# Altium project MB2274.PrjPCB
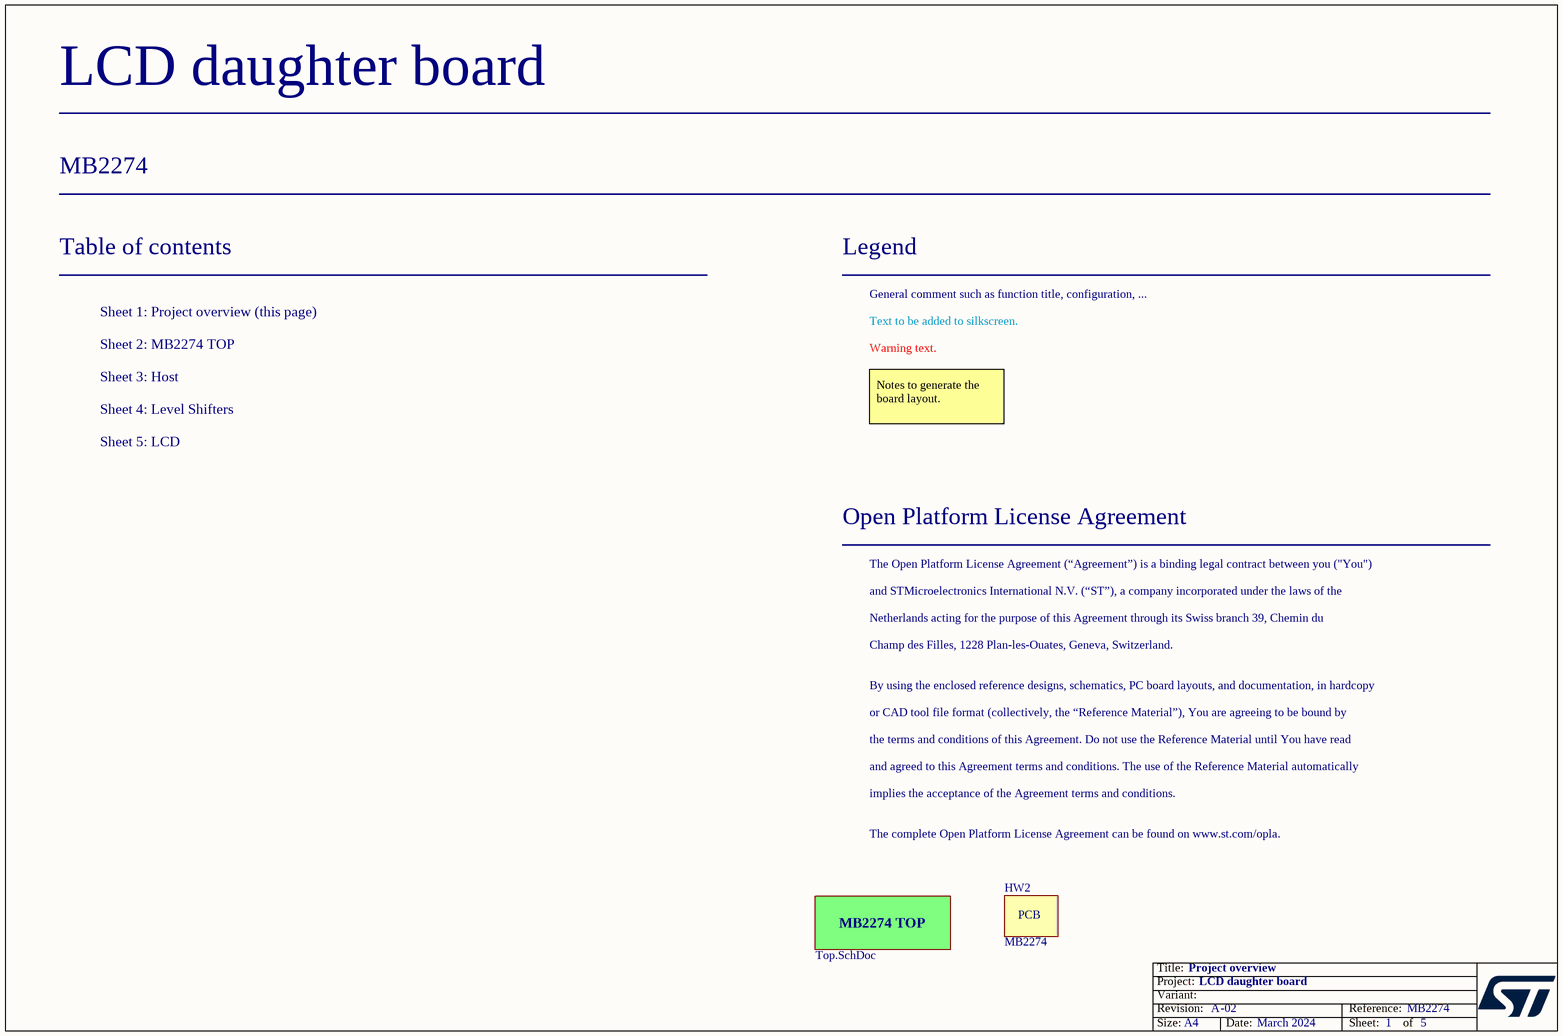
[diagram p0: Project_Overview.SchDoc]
Board_Reference: MB2274; Board_PCB_Revision: A; Board_Name: LCD daughter board; Board_Document_Date: March 2024; Board_Assembly_Revision: 02
5 sheets, 38 parts. Net scope: flat (ports and power ports of the same name join across sheets).
Board file: MB2274.PcbDoc
Sheets:
  Project_Overview.SchDoc
    MB2274 TOP = Top.SchDoc
      Host = Host.SchDoc
      Level Shifter = Level_Shifter.SchDoc
      LCD = LCD.SchDoc

## Sheet Project_Overview.SchDoc: Project overview
size A4; Date: Not used; ApprovedBy: Not used; CheckedBy: Not used; Author: Not used; CompanyName: STMicroelectronics; DrawnBy: Not used; Engineer: Not used; Organization: Not used; Address1: Not used; Address2: Not used; Address3: Not used; Address4: Not used; DocumentNumber: 1; Revision: Not used; SheetNumber: 1; SheetTotal: 5

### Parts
HW2  value MB2274  (hidden comment: PCB)

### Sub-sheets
MB2274 TOP = Top.SchDoc: no entries

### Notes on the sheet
- Table of contents
- Legend
- General comment such as function title, configuration, ...
- Text to be added to silkscreen.
- Warning text.
- Notes to generate the board layout.
- Sheet 1: Project overview (this page)
  Sheet 2: MB2274 TOP
  Sheet 3: Host
  Sheet 4: Level Shifters
  Sheet 5: LCD
- Open Platform License Agreement
- The Open Platform License Agreement (“Agreement”) is a binding legal contract between you ("You")
- and STMicroelectronics International N.V. (“ST”), a company incorporated under the laws of the
- Netherlands acting for the purpose of this Agreement through its Swiss branch 39, Chemin du
- Champ des Filles, 1228 Plan-les-Ouates, Geneva, Switzerland.
- By using the enclosed reference designs, schematics, PC board layouts, and documentation, in hardcopy
- or CAD tool file format (collectively, the “Reference Material”), You are agreeing to be bound by
- the terms and conditions of this Agreement. Do not use the Reference Material until You have read
- and agreed to this Agreement terms and conditions. The use of the Reference Material automatically
- implies the acceptance of the Agreement terms and conditions.
- The complete Open Platform License Agreement can be found on www.st.com/opla.

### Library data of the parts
HW2 = MCD-04586: PCB, MB2274, 4.3inches_TFT_LCD; Part_Preference: Recommended; Manufacturer: H-FAST; ShowFields: YES; ID: 6702

## Sheet Top.SchDoc: Schematic sheet title to update
size A4; Date: Not used; ApprovedBy: Not used; CheckedBy: Not used; Author: Not used; CompanyName: STMicroelectronics; DrawnBy: Not used; Engineer: Not used; Organization: Not used; Address1: Not used; Address2: Not used; Address3: Not used; Address4: Not used; DocumentNumber: 2; Revision: Not used; SheetNumber: 2; SheetTotal: 5
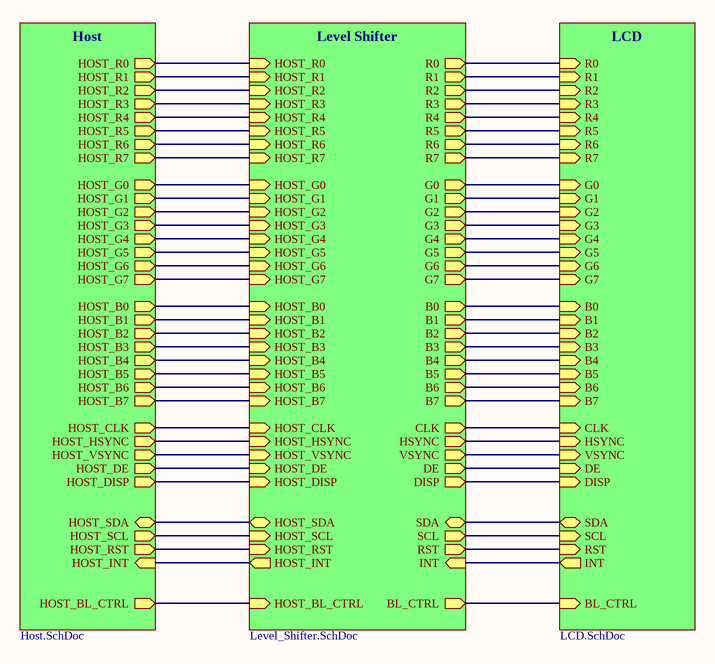
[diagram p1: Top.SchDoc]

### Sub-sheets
Host = Host.SchDoc: HOST_R0 (out), HOST_R1 (out), HOST_R2 (out), HOST_R3 (out), HOST_R4 (out), HOST_R5 (out), HOST_R6 (out), HOST_R7 (out), HOST_G0 (out), HOST_G1 (out), HOST_G2 (out), HOST_G3 (out), HOST_G4 (out), HOST_G5 (out), HOST_G6 (out), HOST_G7 (out), HOST_B0 (out), HOST_B1 (out), HOST_B2 (out), HOST_B3 (out), HOST_B4 (out), HOST_B5 (out), HOST_B6 (out), HOST_B7 (out), HOST_CLK (out), HOST_HSYNC (out), HOST_VSYNC (out), HOST_DE (out), HOST_DISP (out), HOST_SDA (bidir), HOST_SCL (out), HOST_RST (out), HOST_INT (in), HOST_BL_CTRL (out)
LCD = LCD.SchDoc: BL_CTRL (in), R0 (in), R1 (in), R2 (in), R3 (in), R4 (in), R5 (in), R6 (in), R7 (in), G0 (in), G1 (in), G2 (in), G3 (in), G4 (in), G5 (in), G6 (in), G7 (in), B0 (in), B1 (in), B2 (in), B3 (in), B4 (in), B5 (in), B6 (in), B7 (in), CLK (in), HSYNC (in), VSYNC (in), DE (in), DISP (in), SCL (in), SDA (bidir), RST (in), INT (out)
Level Shifter = Level_Shifter.SchDoc: HOST_R0 (in), HOST_R1 (in), HOST_R2 (in), HOST_R3 (in), HOST_R4 (in), HOST_R5 (in), HOST_R6 (in), HOST_R7 (in), HOST_G0 (in), HOST_G1 (in), HOST_G2 (in), HOST_G3 (in), HOST_G4 (in), HOST_G5 (in), HOST_G6 (in), HOST_G7 (in), HOST_B0 (in), HOST_B1 (in), HOST_B2 (in), HOST_B3 (in), HOST_B4 (in), HOST_B5 (in), HOST_B6 (in), HOST_B7 (in), HOST_CLK (in), HOST_HSYNC (in), HOST_VSYNC (in), HOST_DE (in), HOST_DISP (in), HOST_SDA (bidir), HOST_SCL (in), HOST_RST (in), HOST_INT (out), HOST_BL_CTRL (in), R0 (out), R1 (out), R2 (out), R3 (out), R4 (out), R5 (out), R6 (out), R7 (out), G0 (out), G1 (out), G2 (out), G3 (out), G4 (out), G5 (out), G6 (out), G7 (out), B0 (out), B1 (out), B2 (out), B3 (out), B4 (out), B5 (out), B6 (out), B7 (out), CLK (out), HSYNC (out), VSYNC (out), DE (out), DISP (out), SDA (bidir), SCL (out), RST (out), INT (in), BL_CTRL (out)

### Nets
(unnamed): sheet Host/HOST_R0, sheet Level Shifter/HOST_R0
(unnamed): sheet Host/HOST_R1, sheet Level Shifter/HOST_R1  [a separate net that carries the same name]
(unnamed): sheet Host/HOST_R2, sheet Level Shifter/HOST_R2  [a separate net that carries the same name]
(unnamed): sheet Host/HOST_R3, sheet Level Shifter/HOST_R3  [a separate net that carries the same name]
(unnamed): sheet Host/HOST_R4, sheet Level Shifter/HOST_R4  [a separate net that carries the same name]
(unnamed): sheet Host/HOST_R5, sheet Level Shifter/HOST_R5  [a separate net that carries the same name]
(unnamed): sheet Host/HOST_R6, sheet Level Shifter/HOST_R6  [a separate net that carries the same name]
(unnamed): sheet Host/HOST_R7, sheet Level Shifter/HOST_R7  [a separate net that carries the same name]
(unnamed): sheet Host/HOST_G0, sheet Level Shifter/HOST_G0  [a separate net that carries the same name]
(unnamed): sheet Host/HOST_G1, sheet Level Shifter/HOST_G1  [a separate net that carries the same name]
(unnamed): sheet Host/HOST_G2, sheet Level Shifter/HOST_G2  [a separate net that carries the same name]
(unnamed): sheet Host/HOST_G3, sheet Level Shifter/HOST_G3  [a separate net that carries the same name]
(unnamed): sheet Host/HOST_G4, sheet Level Shifter/HOST_G4  [a separate net that carries the same name]
(unnamed): sheet Host/HOST_G5, sheet Level Shifter/HOST_G5  [a separate net that carries the same name]
(unnamed): sheet Host/HOST_G6, sheet Level Shifter/HOST_G6  [a separate net that carries the same name]
(unnamed): sheet Host/HOST_G7, sheet Level Shifter/HOST_G7  [a separate net that carries the same name]
(unnamed): sheet Host/HOST_B0, sheet Level Shifter/HOST_B0  [a separate net that carries the same name]
(unnamed): sheet Host/HOST_B1, sheet Level Shifter/HOST_B1  [a separate net that carries the same name]
(unnamed): sheet Host/HOST_B2, sheet Level Shifter/HOST_B2  [a separate net that carries the same name]
(unnamed): sheet Host/HOST_B3, sheet Level Shifter/HOST_B3  [a separate net that carries the same name]
(unnamed): sheet Host/HOST_B4, sheet Level Shifter/HOST_B4  [a separate net that carries the same name]
(unnamed): sheet Host/HOST_B5, sheet Level Shifter/HOST_B5  [a separate net that carries the same name]
(unnamed): sheet Host/HOST_B6, sheet Level Shifter/HOST_B6  [a separate net that carries the same name]
(unnamed): sheet Host/HOST_B7, sheet Level Shifter/HOST_B7  [a separate net that carries the same name]
(unnamed): sheet Host/HOST_CLK, sheet Level Shifter/HOST_CLK  [a separate net that carries the same name]
(unnamed): sheet Host/HOST_HSYNC, sheet Level Shifter/HOST_HSYNC  [a separate net that carries the same name]
(unnamed): sheet Host/HOST_VSYNC, sheet Level Shifter/HOST_VSYNC  [a separate net that carries the same name]
(unnamed): sheet Host/HOST_DE, sheet Level Shifter/HOST_DE  [a separate net that carries the same name]
(unnamed): sheet Host/HOST_DISP, sheet Level Shifter/HOST_DISP  [a separate net that carries the same name]
(unnamed): sheet Host/HOST_SDA, sheet Level Shifter/HOST_SDA  [a separate net that carries the same name]
(unnamed): sheet Host/HOST_SCL, sheet Level Shifter/HOST_SCL  [a separate net that carries the same name]
(unnamed): sheet Host/HOST_RST, sheet Level Shifter/HOST_RST  [a separate net that carries the same name]
(unnamed): sheet Host/HOST_INT, sheet Level Shifter/HOST_INT  [a separate net that carries the same name]
(unnamed): sheet Host/HOST_BL_CTRL, sheet Level Shifter/HOST_BL_CTRL  [a separate net that carries the same name]
(unnamed): sheet Level Shifter/R0, sheet LCD/R0  [a separate net that carries the same name]
(unnamed): sheet Level Shifter/R1, sheet LCD/R1  [a separate net that carries the same name]
(unnamed): sheet Level Shifter/R2, sheet LCD/R2  [a separate net that carries the same name]
(unnamed): sheet Level Shifter/R3, sheet LCD/R3  [a separate net that carries the same name]
(unnamed): sheet Level Shifter/R4, sheet LCD/R4  [a separate net that carries the same name]
(unnamed): sheet Level Shifter/R5, sheet LCD/R5  [a separate net that carries the same name]
(unnamed): sheet Level Shifter/R6, sheet LCD/R6  [a separate net that carries the same name]
(unnamed): sheet Level Shifter/R7, sheet LCD/R7  [a separate net that carries the same name]
(unnamed): sheet Level Shifter/G0, sheet LCD/G0  [a separate net that carries the same name]
(unnamed): sheet Level Shifter/G1, sheet LCD/G1  [a separate net that carries the same name]
(unnamed): sheet Level Shifter/G2, sheet LCD/G2  [a separate net that carries the same name]
(unnamed): sheet Level Shifter/G3, sheet LCD/G3  [a separate net that carries the same name]
(unnamed): sheet Level Shifter/G4, sheet LCD/G4  [a separate net that carries the same name]
(unnamed): sheet Level Shifter/G5, sheet LCD/G5  [a separate net that carries the same name]
(unnamed): sheet Level Shifter/G6, sheet LCD/G6  [a separate net that carries the same name]
(unnamed): sheet Level Shifter/G7, sheet LCD/G7  [a separate net that carries the same name]
(unnamed): sheet Level Shifter/B0, sheet LCD/B0  [a separate net that carries the same name]
(unnamed): sheet Level Shifter/B1, sheet LCD/B1  [a separate net that carries the same name]
(unnamed): sheet Level Shifter/B2, sheet LCD/B2  [a separate net that carries the same name]
(unnamed): sheet Level Shifter/B3, sheet LCD/B3  [a separate net that carries the same name]
(unnamed): sheet Level Shifter/B4, sheet LCD/B4  [a separate net that carries the same name]
(unnamed): sheet Level Shifter/B5, sheet LCD/B5  [a separate net that carries the same name]
(unnamed): sheet Level Shifter/B6, sheet LCD/B6  [a separate net that carries the same name]
(unnamed): sheet Level Shifter/B7, sheet LCD/B7  [a separate net that carries the same name]
(unnamed): sheet Level Shifter/CLK, sheet LCD/CLK  [a separate net that carries the same name]
(unnamed): sheet Level Shifter/HSYNC, sheet LCD/HSYNC  [a separate net that carries the same name]
(unnamed): sheet Level Shifter/VSYNC, sheet LCD/VSYNC  [a separate net that carries the same name]
(unnamed): sheet Level Shifter/DE, sheet LCD/DE  [a separate net that carries the same name]
(unnamed): sheet Level Shifter/DISP, sheet LCD/DISP  [a separate net that carries the same name]
(unnamed): sheet Level Shifter/SDA, sheet LCD/SDA  [a separate net that carries the same name]
(unnamed): sheet Level Shifter/SCL, sheet LCD/SCL  [a separate net that carries the same name]
(unnamed): sheet Level Shifter/RST, sheet LCD/RST  [a separate net that carries the same name]
(unnamed): sheet Level Shifter/INT, sheet LCD/INT  [a separate net that carries the same name]
(unnamed): sheet Level Shifter/BL_CTRL, sheet LCD/BL_CTRL  [a separate net that carries the same name]

## Sheet Host.SchDoc: Host Connection
size A4; Date: Not used; ApprovedBy: Not used; CheckedBy: Not used; Author: Not used; CompanyName: STMicroelectronics; DrawnBy: Not used; Engineer: Not used; Organization: Not used; Address1: Not used; Address2: Not used; Address3: Not used; Address4: Not used; DocumentNumber: 3; Revision: Not used; SheetNumber: 3; SheetTotal: 5
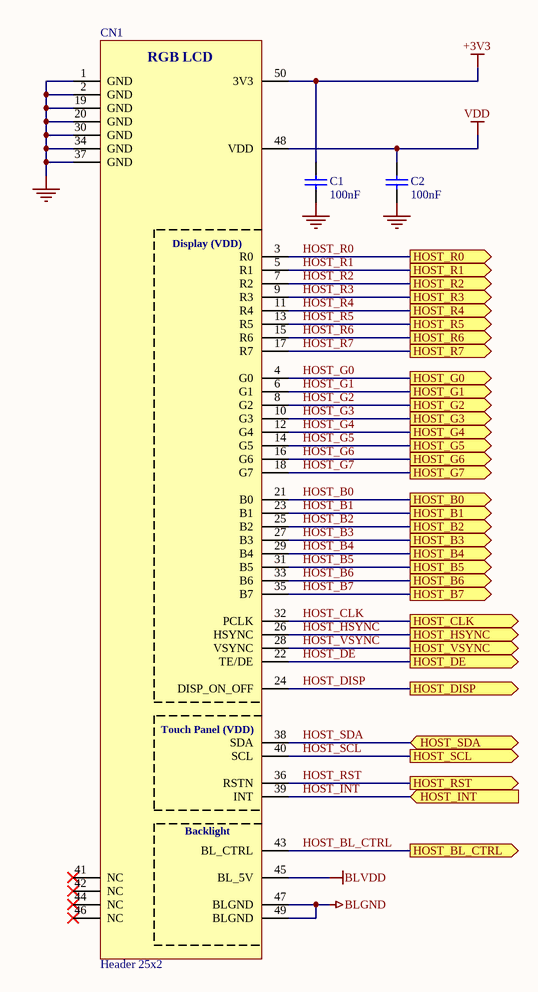
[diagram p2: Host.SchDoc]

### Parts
C1  100nF  [C0603]
C2  100nF  [C0603]
CN1  value Header 25x2  [CON_SAMTEC_FTSH-125-01-F-DV-K]  (hidden comment: Header 25x2 LCD MODULE)

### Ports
HOST_B0 (out), HOST_B1 (out), HOST_B2 (out), HOST_B3 (out), HOST_B4 (out), HOST_B5 (out), HOST_B6 (out), HOST_B7 (out), HOST_BL_CTRL (out), HOST_CLK (out), HOST_DE (out), HOST_DISP (out), HOST_G0 (out), HOST_G1 (out), HOST_G2 (out), HOST_G3 (out), HOST_G4 (out), HOST_G5 (out), HOST_G6 (out), HOST_G7 (out), HOST_HSYNC (out), HOST_INT (in), HOST_R0 (out), HOST_R1 (out), HOST_R2 (out), HOST_R3 (out), HOST_R4 (out), HOST_R5 (out), HOST_R6 (out), HOST_R7 (out), HOST_RST (out), HOST_SCL (out), HOST_SDA (bidir), HOST_VSYNC (out)

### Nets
+3V3: C1.2 CN1.50(3V3)
BLGND: CN1.47(BLGND) CN1.49(BLGND)
BLVDD: CN1.45(BL_5V)
GND: C1.1 C2.1 CN1.1(GND) CN1.2(GND) CN1.19(GND) CN1.20(GND) CN1.30(GND) CN1.34(GND) CN1.37(GND)
VDD: C2.2 CN1.48(VDD)
HOST_B0: CN1.21(B0) ; port HOST_B0
HOST_B1: CN1.23(B1) ; port HOST_B1
HOST_B2: CN1.25(B2) ; port HOST_B2
HOST_B3: CN1.27(B3) ; port HOST_B3
HOST_B4: CN1.29(B4) ; port HOST_B4
HOST_B5: CN1.31(B5) ; port HOST_B5
HOST_B6: CN1.33(B6) ; port HOST_B6
HOST_B7: CN1.35(B7) ; port HOST_B7
HOST_BL_CTRL: CN1.43(BL_CTRL) ; port HOST_BL_CTRL
HOST_CLK: CN1.32(PCLK) ; port HOST_CLK
HOST_DE: CN1.22(TE/DE) ; port HOST_DE
HOST_DISP: CN1.24(DISP_ON_OFF) ; port HOST_DISP
HOST_G0: CN1.4(G0) ; port HOST_G0
HOST_G1: CN1.6(G1) ; port HOST_G1
HOST_G2: CN1.8(G2) ; port HOST_G2
HOST_G3: CN1.10(G3) ; port HOST_G3
HOST_G4: CN1.12(G4) ; port HOST_G4
HOST_G5: CN1.14(G5) ; port HOST_G5
HOST_G6: CN1.16(G6) ; port HOST_G6
HOST_G7: CN1.18(G7) ; port HOST_G7
HOST_HSYNC: CN1.26(HSYNC) ; port HOST_HSYNC
HOST_INT: CN1.39(INT) ; port HOST_INT
HOST_R0: CN1.3(R0) ; port HOST_R0
HOST_R1: CN1.5(R1) ; port HOST_R1
HOST_R2: CN1.7(R2) ; port HOST_R2
HOST_R3: CN1.9(R3) ; port HOST_R3
HOST_R4: CN1.11(R4) ; port HOST_R4
HOST_R5: CN1.13(R5) ; port HOST_R5
HOST_R6: CN1.15(R6) ; port HOST_R6
HOST_R7: CN1.17(R7) ; port HOST_R7
HOST_RST: CN1.36(RSTN) ; port HOST_RST
HOST_SCL: CN1.40(SCL) ; port HOST_SCL
HOST_SDA: CN1.38(SDA) ; port HOST_SDA
HOST_VSYNC: CN1.28(VSYNC) ; port HOST_VSYNC

Not connected (* = marked no-connect by the designer): CN1 41(NC)* 42(NC)* 44(NC)* 46(NC)*

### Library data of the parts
C1 C2 = MCD-00211: Capacitor, MLCC, 100nF, 16V, X7R, +/-10%, 0603, T=0.8mm; Part_Preference: Recommended; Manufacturer: YAGEO; Manufacturer_Part_Number: CC0603KRX7R7BB104; Partial_Alternate_Internal_Part_Number: MCD-01099; Order_Code_RS: 669-8763; Component_Country_Of_Origin: China; ShowFields: YES; ID: 2659
CN1 = MCD-01187: Header, 25x2, 1.27mm, VR, SMD, T=5.97mm; Part_Type: Connector; Part_Preference: Recommended; Manufacturer: SAMTEC; Manufacturer_Part_Number: FTSH-125-01-F-DV-K; Partial_Alternate_Internal_Part_Number: MCD-03150; Order_Code_RS: 208-1518; Component_Country_Of_Origin: China, Costa Rica, Malaysia, USA, Vietnam; ShowFields: YES; ID: 3304

## Sheet Level_Shifter.SchDoc: Level Shifters
size A3; Date: Not used; ApprovedBy: Not used; CheckedBy: Not used; Author: Not used; CompanyName: STMicroelectronics; DrawnBy: Not used; Engineer: Not used; Organization: Not used; Address1: Not used; Address2: Not used; Address3: Not used; Address4: Not used; DocumentNumber: 4; Revision: Not used; SheetNumber: 4; SheetTotal: 5
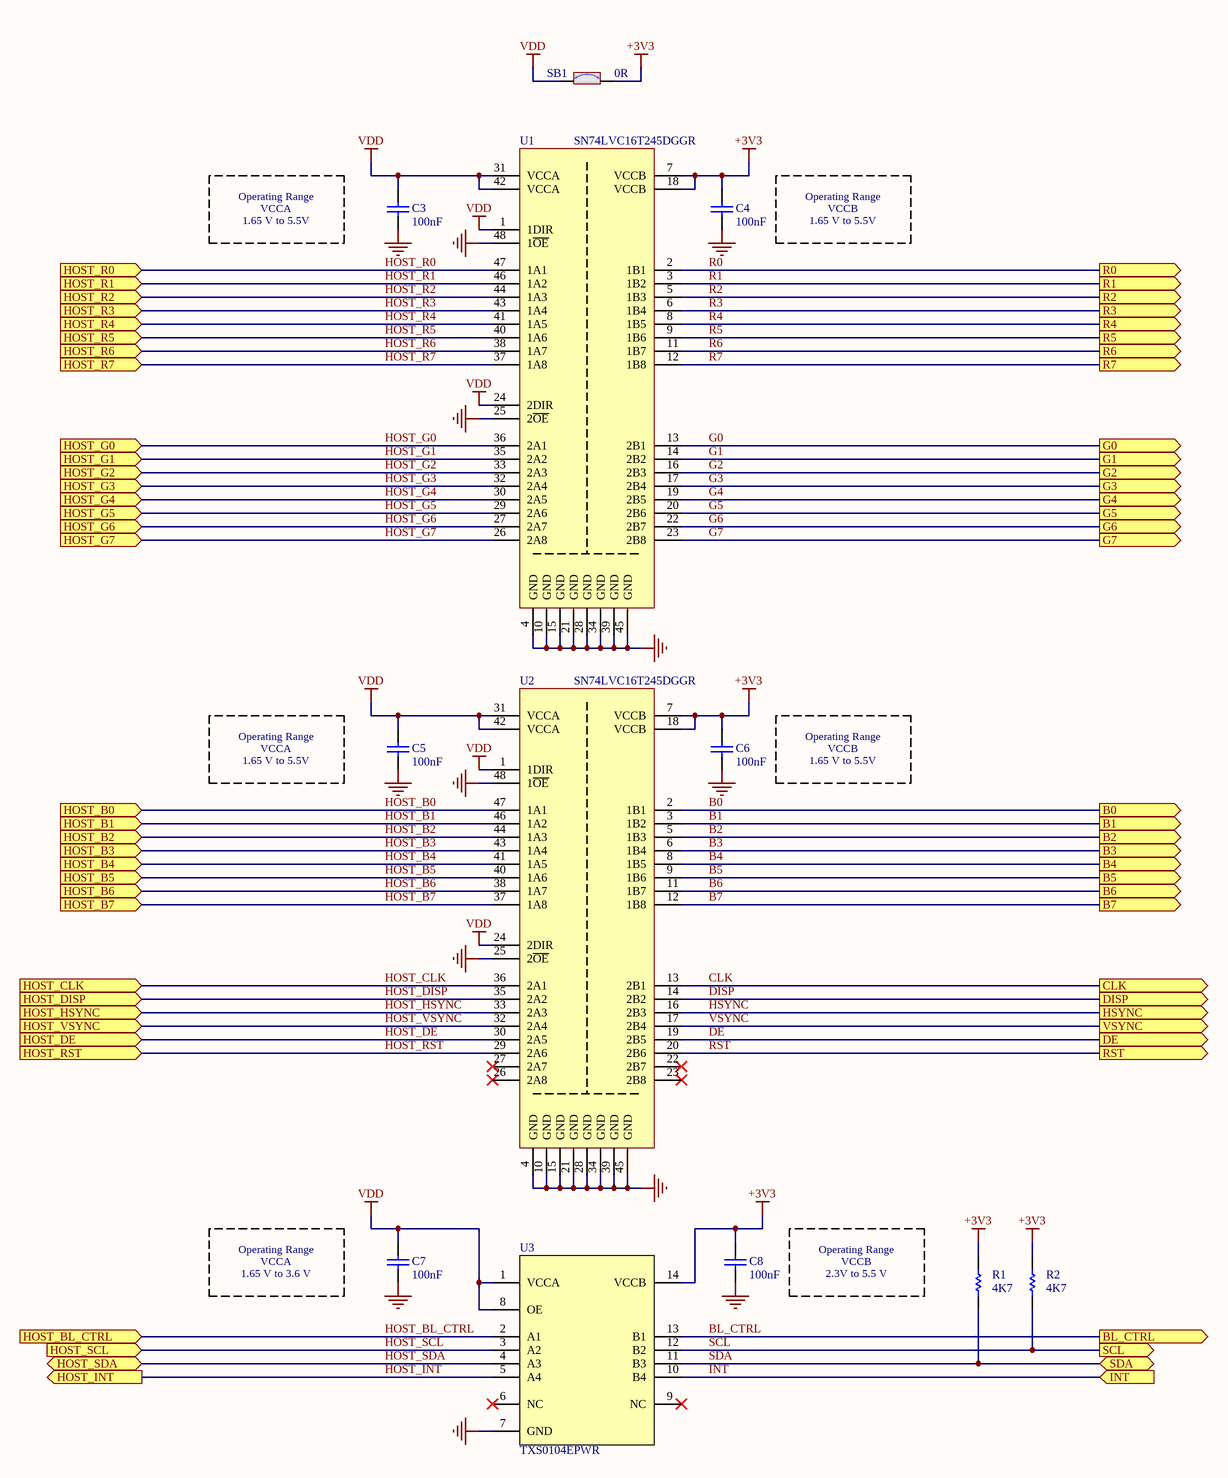
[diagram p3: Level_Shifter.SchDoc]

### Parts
C3  100nF  [C0603]
C4  100nF  [C0603]
C5  100nF  [C0603]
C6  100nF  [C0603]
C7  100nF  [C0603]
C8  100nF  [C0603]
R1  4K7  [R0603]
R2  4K7  [R0603]
SB1  value 0R  [SOLDER-BRIDGE_R0402-0R]  (hidden comment: SB_ON)
U1  SN74LVC16T245DGGR  [ICC_TSSOP48_12P5X6P1_P050]
U2  SN74LVC16T245DGGR  [ICC_TSSOP48_12P5X6P1_P050]
U3  TXS0104EPWR  [ICC_TSSOP14_5X4P40_P065]

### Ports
B0 (out), B1 (out), B2 (out), B3 (out), B4 (out), B5 (out), B6 (out), B7 (out), BL_CTRL (out), CLK (out), DE (out), DISP (out), G0 (out), G1 (out), G2 (out), G3 (out), G4 (out), G5 (out), G6 (out), G7 (out), HOST_B0 (in), HOST_B1 (in), HOST_B2 (in), HOST_B3 (in), HOST_B4 (in), HOST_B5 (in), HOST_B6 (in), HOST_B7 (in), HOST_BL_CTRL (in), HOST_CLK (in), HOST_DE (in), HOST_DISP (in), HOST_G0 (in), HOST_G1 (in), HOST_G2 (in), HOST_G3 (in), HOST_G4 (in), HOST_G5 (in), HOST_G6 (in), HOST_G7 (in), HOST_HSYNC (in), HOST_INT (out), HOST_R0 (in), HOST_R1 (in), HOST_R2 (in), HOST_R3 (in), HOST_R4 (in), HOST_R5 (in), HOST_R6 (in), HOST_R7 (in), HOST_RST (in), HOST_SCL (in), HOST_SDA (bidir), HOST_VSYNC (in), HSYNC (out), INT (in), R0 (out), R1 (out), R2 (out), R3 (out), R4 (out), R5 (out), R6 (out), R7 (out), RST (out), SCL (out), SDA (bidir), VSYNC (out)

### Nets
+3V3: C4.2 C6.2 C8.2 R1.2 R2.2 SB1.2 U1.7(VCCB) U1.18(VCCB) U2.7(VCCB) U2.18(VCCB) U3.14(VCCB)
GND: C3.1 C4.1 C5.1 C6.1 C7.1 C8.1 U1.4(GND) U1.10(GND) U1.15(GND) U1.21(GND) U1.25(2~{OE}) U1.28(GND) U1.34(GND) U1.39(GND) U1.45(GND) U1.48(1~{OE}) U2.4(GND) U2.10(GND) U2.15(GND) U2.21(GND) U2.25(2~{OE}) U2.28(GND) U2.34(GND) U2.39(GND) U2.45(GND) U2.48(1~{OE}) U3.7(GND)
VDD: C3.2 C5.2 C7.2 SB1.1 U1.1(1DIR) U1.24(2DIR) U1.31(VCCA) U1.42(VCCA) U2.1(1DIR) U2.24(2DIR) U2.31(VCCA) U2.42(VCCA) U3.1(VCCA) U3.8(OE)
B0: U2.2(1B1) ; port B0
B1: U2.3(1B2) ; port B1
B2: U2.5(1B3) ; port B2
B3: U2.6(1B4) ; port B3
B4: U2.8(1B5) ; port B4
B5: U2.9(1B6) ; port B5
B6: U2.11(1B7) ; port B6
B7: U2.12(1B8) ; port B7
BL_CTRL: U3.13(B1) ; port BL_CTRL
CLK: U2.13(2B1) ; port CLK
DE: U2.19(2B5) ; port DE
DISP: U2.14(2B2) ; port DISP
G0: U1.13(2B1) ; port G0
G1: U1.14(2B2) ; port G1
G2: U1.16(2B3) ; port G2
G3: U1.17(2B4) ; port G3
G4: U1.19(2B5) ; port G4
G5: U1.20(2B6) ; port G5
G6: U1.22(2B7) ; port G6
G7: U1.23(2B8) ; port G7
HOST_B0: U2.47(1A1) ; port HOST_B0
HOST_B1: U2.46(1A2) ; port HOST_B1
HOST_B2: U2.44(1A3) ; port HOST_B2
HOST_B3: U2.43(1A4) ; port HOST_B3
HOST_B4: U2.41(1A5) ; port HOST_B4
HOST_B5: U2.40(1A6) ; port HOST_B5
HOST_B6: U2.38(1A7) ; port HOST_B6
HOST_B7: U2.37(1A8) ; port HOST_B7
HOST_BL_CTRL: U3.2(A1) ; port HOST_BL_CTRL
HOST_CLK: U2.36(2A1) ; port HOST_CLK
HOST_DE: U2.30(2A5) ; port HOST_DE
HOST_DISP: U2.35(2A2) ; port HOST_DISP
HOST_G0: U1.36(2A1) ; port HOST_G0
HOST_G1: U1.35(2A2) ; port HOST_G1
HOST_G2: U1.33(2A3) ; port HOST_G2
HOST_G3: U1.32(2A4) ; port HOST_G3
HOST_G4: U1.30(2A5) ; port HOST_G4
HOST_G5: U1.29(2A6) ; port HOST_G5
HOST_G6: U1.27(2A7) ; port HOST_G6
HOST_G7: U1.26(2A8) ; port HOST_G7
HOST_HSYNC: U2.33(2A3) ; port HOST_HSYNC
HOST_INT: U3.5(A4) ; port HOST_INT
HOST_R0: U1.47(1A1) ; port HOST_R0
HOST_R1: U1.46(1A2) ; port HOST_R1
HOST_R2: U1.44(1A3) ; port HOST_R2
HOST_R3: U1.43(1A4) ; port HOST_R3
HOST_R4: U1.41(1A5) ; port HOST_R4
HOST_R5: U1.40(1A6) ; port HOST_R5
HOST_R6: U1.38(1A7) ; port HOST_R6
HOST_R7: U1.37(1A8) ; port HOST_R7
HOST_RST: U2.29(2A6) ; port HOST_RST
HOST_SCL: U3.3(A2) ; port HOST_SCL
HOST_SDA: U3.4(A3) ; port HOST_SDA
HOST_VSYNC: U2.32(2A4) ; port HOST_VSYNC
HSYNC: U2.16(2B3) ; port HSYNC
INT: U3.10(B4) ; port INT
R0: U1.2(1B1) ; port R0
R1: U1.3(1B2) ; port R1
R2: U1.5(1B3) ; port R2
R3: U1.6(1B4) ; port R3
R4: U1.8(1B5) ; port R4
R5: U1.9(1B6) ; port R5
R6: U1.11(1B7) ; port R6
R7: U1.12(1B8) ; port R7
RST: U2.20(2B6) ; port RST
SCL: R2.1 U3.12(B2) ; port SCL
SDA: R1.1 U3.11(B3) ; port SDA
VSYNC: U2.17(2B4) ; port VSYNC

Not connected (* = marked no-connect by the designer): U2 22(2B7)* 23(2B8)* 26(2A8)* 27(2A7)*; U3 6(NC)* 9(NC)*

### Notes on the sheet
- Operating Range
  VCCA
  1.65 V to 5.5V
- Operating Range
  VCCB
  1.65 V to 5.5V
- Operating Range
  VCCA
  1.65 V to 3.6 V
- Operating Range
  VCCB
  2.3V to 5.5 V

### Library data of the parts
C3-C8 = MCD-00211: as C1 on sheet Host
R1 R2 = MCD-00219: Resistor, 4K7, 0603, +/-1%, 1/10W; Part_Preference: Recommended; Manufacturer: YAGEO; Manufacturer_Part_Number: RC0603FR-074K7L; Component_Country_Of_Origin: China; ShowFields: YES; ID: 2648
SB1 = MCD-01618: Resistor, 0R, SB0402, 5%, 0.063W; Manufacturer_Part_Number: RC0402JR-070RL; Manufacturer: YAGEO; Part_Preference: Recommended; Order_Code_RS: 618-5804; Component_Country_Of_Origin: China; ID: 3718; ShowFields: YES
U1 U2 = MCD-01074: Bus Transceiver, 16-bit Dual-Supply bus transceiver with configurable Level-Shifting/Voltage translation and Tri-State outputs; Part_Type: IC; Part_Preference: Recommended; Manufacturer: TEXAS INSTRUMENTS; Order_Code_RS: 922-2381; Component_Country_Of_Origin: Malaysia; ShowFields: YES; ID: 3418
U3 = MCD-00274: Voltage Translator, 4-BIT bidirectional voltage-level translator for open-drain and PUSH-PULL applications; Part_Type: IC; Part_Preference: Recommended; Manufacturer: TEXAS INSTRUMENTS; Order_Code_RS: 921-5065; Component_Country_Of_Origin: Malaysia; ShowFields: YES; ID: 2595

## Sheet LCD.SchDoc: LCD
size A4; Date: Not used; ApprovedBy: Not used; CheckedBy: Not used; Author: Not used; CompanyName: STMicroelectronics; DrawnBy: Not used; Engineer: Not used; Organization: Not used; Address1: Not used; Address2: Not used; Address3: Not used; Address4: Not used; DocumentNumber: 5; Revision: Not used; SheetNumber: 5; SheetTotal: 5
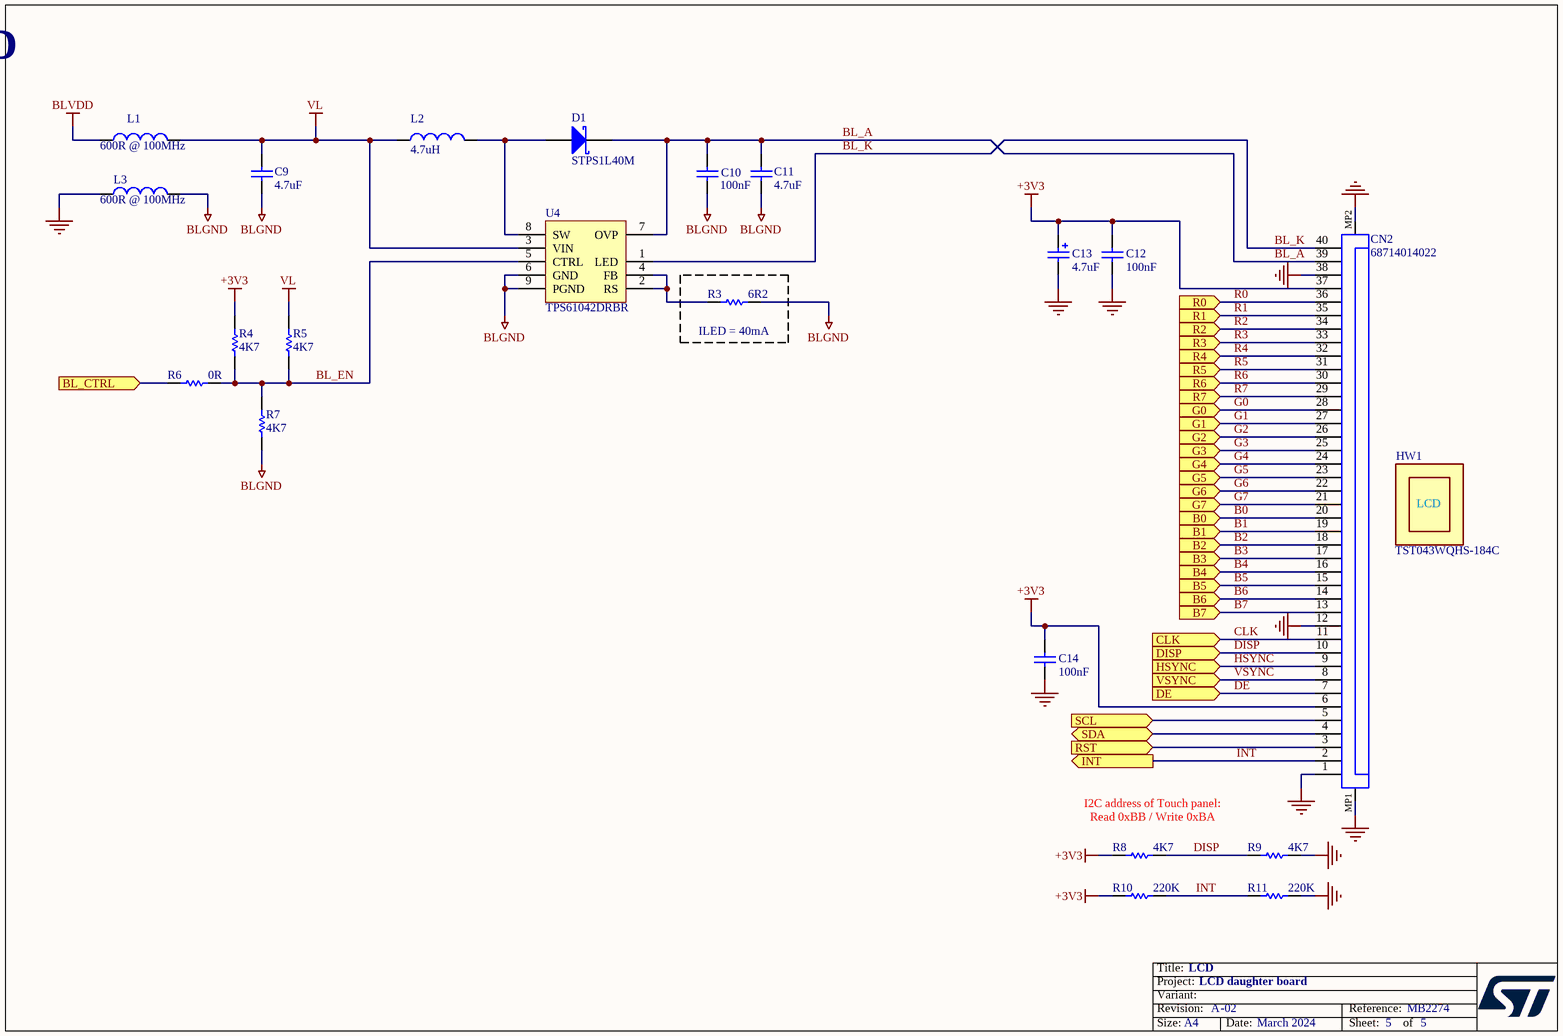
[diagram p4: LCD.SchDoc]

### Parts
C9  value 4.7uF  [C1206_H1P25]  (hidden comment: Capacitor)
C10  value 100nF  [C0603]  (hidden comment: Capacitor)
C11  value 4.7uF  [C1206_H1P25]  (hidden comment: Capacitor)
C12  value 100nF  [C0603]  (hidden comment: Capacitor)
C13  value 4.7uF  [CPOL_TAJ-A_1206_H180]  (hidden comment: Cap_POL_TANA)
C14  value 100nF  [C0603]  (hidden comment: Capacitor)
CN2  68714014022  [CON_WE_68714014022]
D1  STPS1L40M  [DIO_DO216-AA]
HW1  value TST043WQHS-184C  [LCD_DRAWING_TSD-TST043WQHS-184C]  (hidden comment: LCD_MODULE)  (mechanical)
L1  value 600R @ 100MHz  [L0603]  (hidden comment: BEAD)
L2  value 4.7uH  [L1210_LQH]  (hidden comment: Inductor)
L3  value 600R @ 100MHz  [L0603]  (hidden comment: BEAD)
R3  value 6R2  [R0805_H0P5]  (hidden comment: Resistor)
R4  value 4K7  [R0603]  (hidden comment: Resistor)
R5  value 4K7  [R0603]  (hidden comment: Resistor)
R6  value 0R  [R0603]  (hidden comment: Resistor)
R7  value 4K7  [R0603]  (hidden comment: Resistor)
R8  value 4K7  [R0603]  (hidden comment: Resistor)
R9  value 4K7  [R0603]  (hidden comment: Resistor)
R10  value 220K  [R0603]  (hidden comment: Resistor)
R11  value 220K  [R0603]  (hidden comment: Resistor)
U4  value TPS61042DRBR  [ICC_VSON8-EPAD_3X3_P065]  (hidden comment: TPS61042DRB)

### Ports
B0 (in), B1 (in), B2 (in), B3 (in), B4 (in), B5 (in), B6 (in), B7 (in), BL_CTRL (in), CLK (in), DE (in), DISP (in), G0 (in), G1 (in), G2 (in), G3 (in), G4 (in), G5 (in), G6 (in), G7 (in), HSYNC (in), INT (out), R0 (in), R1 (in), R2 (in), R3 (in), R4 (in), R5 (in), R6 (in), R7 (in), RST (in), SCL (in), SDA (bidir), VSYNC (in)

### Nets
+3V3: C12.2 C13.1 C14.2 CN2.6 CN2.37 R4.1 R8.2 R10.2
BLGND: C9.1 C10.1 C11.1 L3.2 R3.1 R7.2 U4.6(GND) U4.9(PGND)
BLVDD: L1.1
GND: C12.1 C13.2 C14.1 CN2.1 CN2.12 CN2.38 CN2.MP1 CN2.MP2 L3.1 R9.1 R11.1
VL: C9.2 L1.2 L2.1 R5.1 U4.3(VIN)
B0: CN2.20 ; port B0
B1: CN2.19 ; port B1
B2: CN2.18 ; port B2
B3: CN2.17 ; port B3
B4: CN2.16 ; port B4
B5: CN2.15 ; port B5
B6: CN2.14 ; port B6
B7: CN2.13 ; port B7
BL_A: C10.2 C11.2 CN2.39 D1.2(K) U4.7(OVP)
BL_CTRL: R6.1 ; port BL_CTRL
BL_EN: R4.2 R5.2 R6.2 R7.1 U4.5(CTRL)
BL_K: CN2.40 U4.1(LED)
CLK: CN2.11 ; port CLK
DE: CN2.7 ; port DE
DISP: CN2.10 R8.1 R9.2 ; port DISP
G0: CN2.28 ; port G0
G1: CN2.27 ; port G1
G2: CN2.26 ; port G2
G3: CN2.25 ; port G3
G4: CN2.24 ; port G4
G5: CN2.23 ; port G5
G6: CN2.22 ; port G6
G7: CN2.21 ; port G7
HSYNC: CN2.9 ; port HSYNC
INT: CN2.2 R10.1 R11.2 ; port INT
R0: CN2.36 ; port R0
R1: CN2.35 ; port R1
R2: CN2.34 ; port R2
R3: CN2.33 ; port R3
R4: CN2.32 ; port R4
R5: CN2.31 ; port R5
R6: CN2.30 ; port R6
R7: CN2.29 ; port R7
RST: CN2.3 ; port RST
SCL: CN2.5 ; port SCL
SDA: CN2.4 ; port SDA
VSYNC: CN2.8 ; port VSYNC
NetD1_1: D1.1(A) L2.2 U4.8(SW)
NetR3_2: R3.2 U4.2(RS) U4.4(FB)

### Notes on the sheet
- (near R3) ILED = 40mA
- I2C address of Touch panel:
  Read 0xBB / Write 0xBA

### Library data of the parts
C9 C11 = MCD-00013: Capacitor, MLCC, 4.7uF, 50V, X7R, +/-10%, 1206, T=1.27mm; Part_Preference: Recommended; Manufacturer: AVX; Manufacturer_Part_Number: 12065C475KAT2A; Order_Code_RS: 1908177; Component_Country_Of_Origin: China, Malaysia; ShowFields: YES; ID: 2466
C10 = MCD-01099: Capacitor, MLCC, 100nF, 50V, X7R, +/-10%, 0603, T=0.8mm; BMS_Part_Number: 9142278; Part_Preference: Recommended; Manufacturer: YAGEO; Manufacturer_Part_Number: CC0603KRX7R9BB104; Order_Code_RS: 669-8767; Component_Country_Of_Origin: China; ShowFields: YES; ID: 3397
C12 C14 = MCD-00211: as C1 on sheet Host
C13 = MCD-00007: Capacitor, Tantalum, 4.7uF, 16V, 4R, +/-10%, 3216, T=1.6mm; Part_Preference: Recommended; Manufacturer: AVX; Manufacturer_Part_Number: TAJA475K016R; Partial_Alternate_Internal_Part_Number: MCD-03149; Order_Code_RS: 197269; Component_Country_Of_Origin: El Salvador; ShowFields: YES; ID: 2473
CN2 = MCD-02724: Socket_FFC/FPC, 40pins, 0.5mm, RA, SMD, T=2.1mm; Part_Type: Connector; Part_Preference: Recommended; Manufacturer: WURTH ELEKTRONIK; Value: Socket_FFC/FPC_68714014022; Order_Code_RS: 763-6732; ShowFields: YES; ID: 4821; Component_Country_Of_Origin: China°
D1 = MCD-00033: Diode, Schottky, 0V46, 1A, 40V, DO216-AA; BMS_Part_Number: 9151085; Part_Preference: Recommended; Manufacturer: STMICROELECTRONICS; Manufacturer_HQ_COO: EU; Component_Country_Of_Origin: China; ShowFields: YES; ID: 2485; Order_Code_RS: 189-4505
HW1 = MCD-04212: LCD, TFT, 4.3-inch, RGB, 480x272 pixels, 16.7M Color; Part_Type: Display; Part_Preference: Recommended; Manufacturer: TEAM SOURCE DISPLAY; Order_Code_RS: NA; ShowFields: YES; ID: 6328
L1 L3 = MCD-00047: Ferrite bead, 600R @1 00MHz, +/-25%, 350mA, 0R5, 0603, T=0.8mm; Part_Type: Inductor; Part_Preference: Recommended; Manufacturer: TAI-TECH; Manufacturer_Part_Number: FCM1608KF-601T03; Partial_Alternate_Internal_Part_Number: MCD-02959; Component_Country_Of_Origin: Unknown; ShowFields: YES; ID: 2546
L2 = MCD-00048: Inductor, 4.7uH, +/-30%, 1A, 180mR, 1210, T=1.7mm; Part_Preference: Recommended; Manufacturer: MURATA; Manufacturer_Part_Number: LQH32PN4R7NN0L; Order_Code_RS: 2470296; Component_Country_Of_Origin: Japan°°; ShowFields: YES; ID: 2544
R3 = MCD-02728: Resistor, 6R2, 0805, +/-1%, 1/8W; Part_Preference: Recommended; Manufacturer: YAGEO; Manufacturer_Part_Number: RC0805FR-076R2L; ShowFields: YES; ID: 4840; Component_Country_Of_Origin: China
R4 R5 R7-R9 = MCD-00219: as R1 on sheet Level_Shifter
R6 = MCD-00056: Resistor, 0R, 0603, +/-5%, 1/10W; Part_Preference: Recommended; Manufacturer: YAGEO; Manufacturer_Part_Number: RC0603JR-070RL; Order_Code_RS: 9233130RL; Component_Country_Of_Origin: China; ShowFields: YES; ID: 2536
R10 R11 = MCD-00347: Resistor, 220K, 0603, +/-1%, 1/10W; Part_Preference: Recommended; Manufacturer: YAGEO; Manufacturer_Part_Number: RC0603FR-07220KL; Component_Country_Of_Origin: China; ShowFields: YES; ID: 2930
U4 = MCD-02727: LED driver, High frequency boost converter with constant current output; Part_Type: IC; Part_Preference: Recommended; Manufacturer: TEXAS INSTRUMENTS; ShowFields: YES; ID: 4839; Component_Country_Of_Origin: Malaysia

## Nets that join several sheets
+3V3: Host (C1.2 CN1.50), Level_Shifter (11 pins), LCD (8 pins)
BLGND: Host (CN1.47 CN1.49), LCD (8 pins)
BLVDD: Host (CN1.45), LCD (L1.1)
GND: Host (9 pins), Level_Shifter (27 pins), LCD (11 pins)
VDD: Host (C2.2 CN1.48), Level_Shifter (14 pins)
B0: Level_Shifter (U2.2), LCD (CN2.20)
B1: Level_Shifter (U2.3), LCD (CN2.19)
B2: Level_Shifter (U2.5), LCD (CN2.18)
B3: Level_Shifter (U2.6), LCD (CN2.17)
B4: Level_Shifter (U2.8), LCD (CN2.16)
B5: Level_Shifter (U2.9), LCD (CN2.15)
B6: Level_Shifter (U2.11), LCD (CN2.14)
B7: Level_Shifter (U2.12), LCD (CN2.13)
BL_CTRL: Level_Shifter (U3.13), LCD (R6.1)
CLK: Level_Shifter (U2.13), LCD (CN2.11)
DE: Level_Shifter (U2.19), LCD (CN2.7)
DISP: Level_Shifter (U2.14), LCD (CN2.10 R8.1 R9.2)
G0: Level_Shifter (U1.13), LCD (CN2.28)
G1: Level_Shifter (U1.14), LCD (CN2.27)
G2: Level_Shifter (U1.16), LCD (CN2.26)
G3: Level_Shifter (U1.17), LCD (CN2.25)
G4: Level_Shifter (U1.19), LCD (CN2.24)
G5: Level_Shifter (U1.20), LCD (CN2.23)
G6: Level_Shifter (U1.22), LCD (CN2.22)
G7: Level_Shifter (U1.23), LCD (CN2.21)
HOST_B0: Host (CN1.21), Level_Shifter (U2.47)
HOST_B1: Host (CN1.23), Level_Shifter (U2.46)
HOST_B2: Host (CN1.25), Level_Shifter (U2.44)
HOST_B3: Host (CN1.27), Level_Shifter (U2.43)
HOST_B4: Host (CN1.29), Level_Shifter (U2.41)
HOST_B5: Host (CN1.31), Level_Shifter (U2.40)
HOST_B6: Host (CN1.33), Level_Shifter (U2.38)
HOST_B7: Host (CN1.35), Level_Shifter (U2.37)
HOST_BL_CTRL: Host (CN1.43), Level_Shifter (U3.2)
HOST_CLK: Host (CN1.32), Level_Shifter (U2.36)
HOST_DE: Host (CN1.22), Level_Shifter (U2.30)
HOST_DISP: Host (CN1.24), Level_Shifter (U2.35)
HOST_G0: Host (CN1.4), Level_Shifter (U1.36)
HOST_G1: Host (CN1.6), Level_Shifter (U1.35)
HOST_G2: Host (CN1.8), Level_Shifter (U1.33)
HOST_G3: Host (CN1.10), Level_Shifter (U1.32)
HOST_G4: Host (CN1.12), Level_Shifter (U1.30)
HOST_G5: Host (CN1.14), Level_Shifter (U1.29)
HOST_G6: Host (CN1.16), Level_Shifter (U1.27)
HOST_G7: Host (CN1.18), Level_Shifter (U1.26)
HOST_HSYNC: Host (CN1.26), Level_Shifter (U2.33)
HOST_INT: Host (CN1.39), Level_Shifter (U3.5)
HOST_R0: Host (CN1.3), Level_Shifter (U1.47)
HOST_R1: Host (CN1.5), Level_Shifter (U1.46)
HOST_R2: Host (CN1.7), Level_Shifter (U1.44)
HOST_R3: Host (CN1.9), Level_Shifter (U1.43)
HOST_R4: Host (CN1.11), Level_Shifter (U1.41)
HOST_R5: Host (CN1.13), Level_Shifter (U1.40)
HOST_R6: Host (CN1.15), Level_Shifter (U1.38)
HOST_R7: Host (CN1.17), Level_Shifter (U1.37)
HOST_RST: Host (CN1.36), Level_Shifter (U2.29)
HOST_SCL: Host (CN1.40), Level_Shifter (U3.3)
HOST_SDA: Host (CN1.38), Level_Shifter (U3.4)
HOST_VSYNC: Host (CN1.28), Level_Shifter (U2.32)
HSYNC: Level_Shifter (U2.16), LCD (CN2.9)
INT: Level_Shifter (U3.10), LCD (CN2.2 R10.1 R11.2)
R0: Level_Shifter (U1.2), LCD (CN2.36)
R1: Level_Shifter (U1.3), LCD (CN2.35)
R2: Level_Shifter (U1.5), LCD (CN2.34)
R3: Level_Shifter (U1.6), LCD (CN2.33)
R4: Level_Shifter (U1.8), LCD (CN2.32)
R5: Level_Shifter (U1.9), LCD (CN2.31)
R6: Level_Shifter (U1.11), LCD (CN2.30)
R7: Level_Shifter (U1.12), LCD (CN2.29)
RST: Level_Shifter (U2.20), LCD (CN2.3)
SCL: Level_Shifter (R2.1 U3.12), LCD (CN2.5)
SDA: Level_Shifter (R1.1 U3.11), LCD (CN2.4)
VSYNC: Level_Shifter (U2.17), LCD (CN2.8)

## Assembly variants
LCD43-RGB: not fitted R4 R5 R8 R10 SB1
